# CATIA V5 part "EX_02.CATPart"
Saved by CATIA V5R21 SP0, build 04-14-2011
Part number: Part1
Material "DS Gold": density 7860 kg/m3, Young's modulus 2e+11 Pa, Poisson ratio 0.266
Bounding box of the stored display mesh (mm): x 0 to 50, y -60 to 220, z -50 to 446
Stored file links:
  G:\CATIA\Class\Class_3D\EX_02.CATPart
  C:\Program Files (x86)\Dassault Systemes\B21\intel_a\startup\materials\DS_star.jpg
  C:\Program Files (x86)\Dassault Systemes\B21\intel_a\startup\materials\yellow_env_512x512.jpg
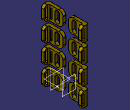
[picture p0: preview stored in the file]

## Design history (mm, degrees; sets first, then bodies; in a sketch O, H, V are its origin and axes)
Body1 (main body), material "DS Gold"
  Sketch1 on yz-plane, origin (0, 0, 0), H (0, 1, 0), V (0, 0, 1)
    line L1 (60, 20) -> (60, -20)
    line L2 (30, -50) -> (-60, -50)
    line L3 (-60, -50) -> (-60, 50)
    line L4 (-60, 50) -> (30, 50)
    point P1 (60, 50)
    point P3 (-60, 50)
    arc A1 centre (30, 20) radius 30 from (30, 50) to (60, 20) cw
    point P4 (30, 50)
    point P5 (60, 20)
    point P7 (60, -20)
    point P8 (30, -50)
    arc A2 centre (30, -20) radius 30 from (30, -50) to (60, -20) ccw
    construction line L5 (20, 25.9999) -> (20, -25.9999)
    point P10 (20, 25.9999)
    point P11 (20, -25.9999)
    line L6 (35, 25.9999) -> (35, -25.9999)
    line L7 (5, -25.9999) -> (5, 25.9999)
    arc A3 centre (20, -25.9999) radius 15 from (35, -25.9999) to (5, -25.9999) cw
    arc A4 centre (20, 25.9999) radius 15 from (5, 25.9999) to (35, 25.9999) cw
    distance P3 P1 = 120
    radius A1 = 30
    distance L5 L6 = 15
    distance L5 V = 20
    vertical: L1 V, L3 V, L5 V
    horizontal: L2 H, L4 H
    equidistance: L1 L3 O, L2 L4 O
    coincidence: L4 P1, L1 P1
    tangency: A1 L4, A1 L1, A3 L6, A4 L6, A3 L7, A4 L7
    symmetry: P5 P7 H, P4 P8 H, A1 A2 H, P11 P10 H
  Pad1: profile Sketch1, direction (1, 0, 0), length 20
  Sketch2 on face of Pad1 from Sketch1.L3, origin (0, -60, 0), H (1, 0, 0), V (0, 0, 1)
    line L1 (20, 50) -> (20, -50)
    line L2 (20, -50) -> (30, -50)
    arc A1 centre (30, -30) radius 20 from (30, -50) to (50, -30) ccw
    line L3 (50, -30) -> (50, 30)
    arc A2 centre (30, 30) radius 20 from (50, 30) to (30, 50) ccw
    line L4 (30, 50) -> (20, 50)
    reference projected line E1 (20, 50) -> (20, -50) from edge [face of Pad1 from Sketch1.L3 | end face of Pad1]
    reference projected line E2 (0, 50) -> (20, 50) from edge [face of Pad1 from Sketch1.L3 | face of Pad1 from Sketch1.L4]
    construction line L5 (35.4238, 30) -> (35.4238, -30)
    point P9 (35.4238, 30)
    point P10 (35.4238, -30)
    line L6 (41.4238, 30) -> (41.4238, -30)
    line L7 (29.4238, -30) -> (29.4238, 30)
    arc A3 centre (35.4238, -30) radius 6 from (41.4238, -30) to (29.4238, -30) cw
    arc A4 centre (35.4238, 30) radius 6 from (29.4238, 30) to (41.4238, 30) cw
    length L1 = 100
    distance L3 L1 = 30
    radius A1 = 20
    radius A2 = 20
    length L4 = 10
    distance L5 L6 = 6
    length L5 = 60
    vertical: L1 V, L5 V
    horizontal: L2 H, L4 H
    tangency: A1 L2, L3 A1, A2 L3, A3 L6, A4 L6, A3 L7, A4 L7
    coincidence: L1 E1, L4 E2
    symmetry: P9 P10 H
  Pad2: profile Sketch2, direction (0, 1, 0), length 20
  Sketch3 on end face of Pad1, origin (20, 0, 0), H (0, 1, 0), V (0, 0, 1)
    construction line L1 (-21.2925, 31.4472) -> (-21.2925, -29.5478)
    line L2 (-16.3689, 31.4472) -> (-16.3689, -29.5478)
    line L3 (-26.2161, -29.5478) -> (-26.2161, 31.4472)
    arc A1 centre (-21.2925, -29.5478) radius 4.9236 from (-16.3689, -29.5478) to (-26.2161, -29.5478) cw
    arc A2 centre (-21.2925, 31.4472) radius 4.9236 from (-26.2161, 31.4472) to (-16.3689, 31.4472) cw
    distance L1 L2 = 4.9236
    vertical: L1 V
    tangency: A1 L2, A2 L2, A1 L3, A2 L3
  Pocket1: profile Sketch3, direction (-1, 0, 0), through (limit type 6)
  Fillet1: radius 10, on edge [start face of Pad1 | face of Pad2]
  Fillet2: radius 7, on edge [end face of Pad2 | end face of Pad1]
  Plane1: type Offset, RefPlane zx-plane, Offset 80
  Mirror1: of the body so far, about Plane1
  RectPattern1: of the body so far, direction 1 instances 4, spacing 132, along Plane1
